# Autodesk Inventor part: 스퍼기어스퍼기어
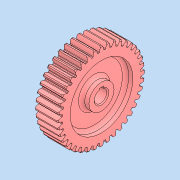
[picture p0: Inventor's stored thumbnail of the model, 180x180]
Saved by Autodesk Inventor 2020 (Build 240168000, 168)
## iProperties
Created: 2024-11
Part Number: 스퍼기어스퍼기어
Material: 강철, 탄소
Document SubType Name: Modeling
Designer: 1강의실14
Density: 7.85 g/cm^3
Appearance: 기본값
Author: jhkim
Sending System: Autodesk Inventor 2025
Preprocessor: ST-DEVELOPER v20
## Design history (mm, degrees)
feature "솔리드1"
node "솔리드2"
